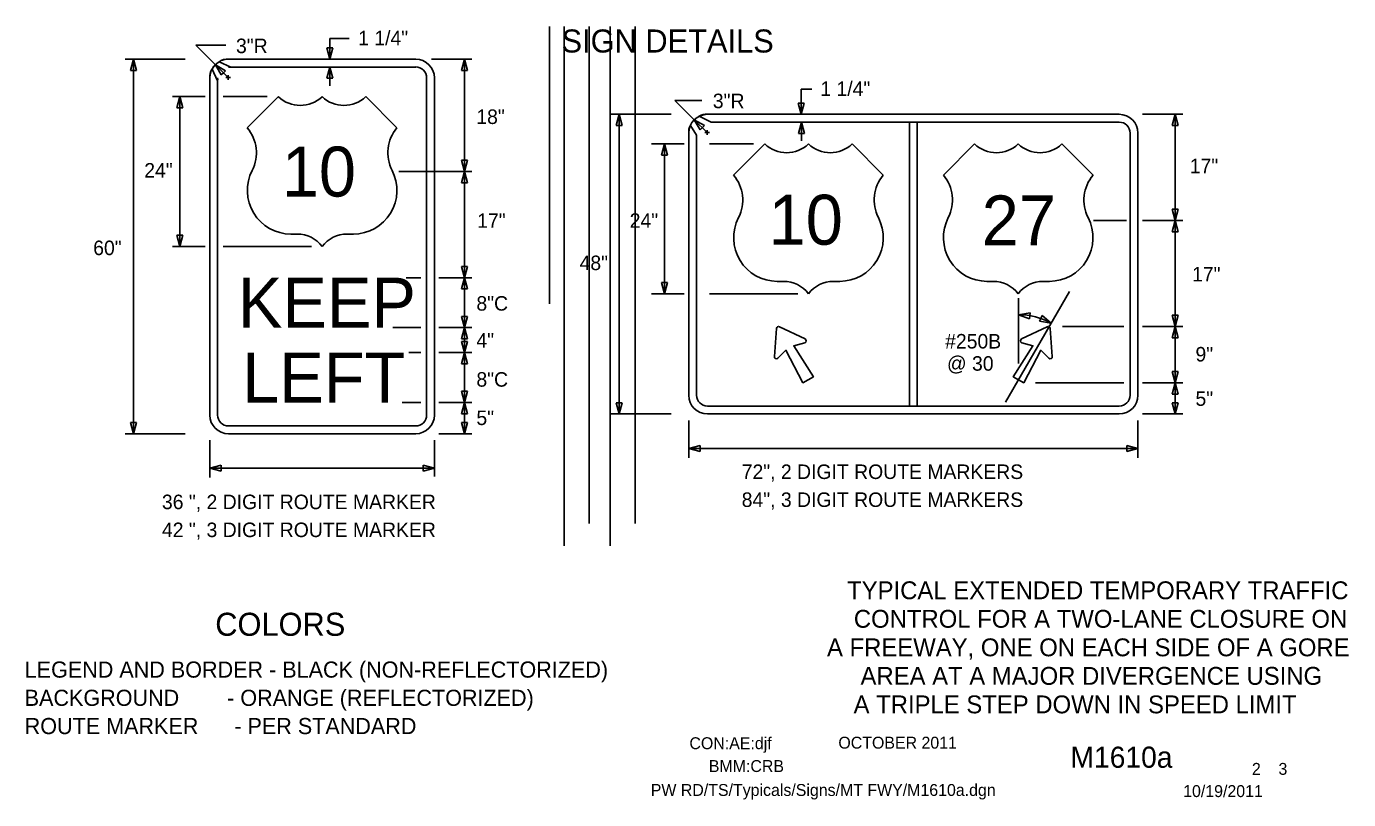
# Model space of a CAD drawing. Extents: x 16554 to 19508, y 5694 to 7079.
# Drawn here: x 17774 to 18463, y 5932 to 6334 of the extents above; entities that cross this region are included whole.
import ezdxf

# ---------------------------------------------------------------- set-up
doc = ezdxf.new("R2010")
doc.units = 0
for name, color, linetype in [('ALI_LEGAL_EX', 7, 'Continuous'), ('BORDER', 7, 'Continuous'), ('BORDER_SIGNAL_WO', 7, 'Continuous'), ('TRAFFIC_SIGNS_PR', 7, 'Continuous'), ('TYPICAL_EX', 7, 'Continuous'), ('TYPICAL_TEXT_DIMEN_PR', 7, 'Continuous')]:
    doc.layers.add(name, color=color, linetype=linetype)

msp = doc.modelspace()

# ---------------------------------------------------------------- linework, layer by layer
at = {"layer": 'ALI_LEGAL_EX'}
for p, q in [((18046.81, 6189.84), (18046.81, 6334.29)), ((18054.48, 6334.29), (18054.48, 6206.79)), ((18054.48, 6334.29), (18054.48, 6063.94)), ((18067.45, 6075.61), (18067.45, 6334.29)), ((18078.48, 6334.29), (18078.48, 6206.79)), ((18078.48, 6334.29), (18078.48, 6063.94)), ((18091.45, 6075.61), (18091.45, 6334.29))]:
    msp.add_line(p, q, dxfattribs=at)
at = {"layer": 'TRAFFIC_SIGNS_PR'}
for p, q in [((17879.58, 6317.25), (17977.08, 6317.25)), ((17872, 6313.63), (17870.99, 6312.12)), ((17871.02, 6312.05), (17873.89, 6306.01)), ((17880.78, 6313.18), (17874.69, 6315.93)), ((17977.08, 6313.18), (17879.58, 6313.18)), ((17869.83, 6132), (17869.83, 6307.5)), ((17873.89, 6307.5), (17873.89, 6132)), ((17982.77, 6132), (17982.77, 6307.5)), ((17986.83, 6307.5), (17986.83, 6132)), ((18120.27, 6282.81), (18123.41, 6277.76)), ((18131.06, 6284.5), (18124.82, 6287.51)), ((18129.1, 6288.55), (18343.6, 6288.55)), ((18129.1, 6288.55), (18343.6, 6288.55)), ((18131.04, 6284.49), (18234.32, 6284.49)), ((18343.6, 6284.49), (18131.04, 6284.49)), ((18234.32, 6284.49), (18234.32, 6136.61)), ((18238.38, 6284.49), (18238.38, 6136.61)), ((18238.38, 6284.49), (18343.6, 6284.49)), ((18119.35, 6278.8), (18119.35, 6142.3)), ((18119.35, 6142.3), (18119.35, 6278.8)), ((18123.41, 6277.75), (18123.41, 6142.3)), ((18123.41, 6277.75), (18123.41, 6142.3)), ((18349.29, 6278.8), (18349.29, 6233.05)), ((18349.29, 6142.3), (18349.29, 6278.8)), ((18353.35, 6278.8), (18353.35, 6142.3)), ((18353.35, 6278.8), (18353.35, 6142.3)), ((18349.29, 6233.05), (18349.29, 6142.3)), ((18163.95, 6162.41), (18165.1, 6177.12)), ((18166.62, 6177.99), (18179.93, 6171.63)), ((18306.08, 6177.99), (18292.77, 6171.63)), ((18308.75, 6162.41), (18307.6, 6177.12)), ((18129.1, 6136.61), (18343.6, 6136.61)), ((18129.1, 6132.55), (18343.6, 6132.55)), ((18343.6, 6132.55), (18129.1, 6132.55)), ((17879.58, 6126.31), (17977.08, 6126.31)), ((17977.08, 6122.25), (17879.58, 6122.25))]:
    msp.add_line(p, q, dxfattribs=at)
for points in [[(18131.04, 6284.49), (18131.03, 6284.49)], [(18123.41, 6277.76), (18123.41, 6277.75)], [(18179.77, 6169.66), (18174.04, 6168.09), (18184.26, 6151.92), (18178.86, 6148.8), (18169.97, 6165.74), (18165.74, 6161.57)], [(18292.93, 6169.66), (18298.66, 6168.09), (18288.44, 6151.92), (18293.84, 6148.8), (18302.73, 6165.74), (18306.96, 6161.57)]]:
    msp.add_lwpolyline(points, dxfattribs=at)
msp.add_lwpolyline([(18234.32, 6284.49), (18238.38, 6284.49), (18238.38, 6136.61), (18234.32, 6136.61)], close=True, dxfattribs=at)
for centre, radius, start, end in [((17879.58, 6307.5), 9.75, 90, 180), ((17878.99, 6309.67), 7.6, 85.58319, 124.53531), ((17977.08, 6307.5), 9.75, 0, 90), ((17876.86, 6308.09), 7.06, 145.86811, 184.82317), ((17880.18, 6317.61), 4.47, 262.2432, 277.7568), ((17977.08, 6307.5), 5.69, 0, 90), ((17868.43, 6306.75), 5.51, 352.24294, 7.75653), ((18125.48, 6279.5), 6.17, 147.60925, 186.56283), ((18129.1, 6278.8), 9.75, 90, 180), ((18129.1, 6278.8), 9.75, 90, 180), ((18128.42, 6281.98), 6.6, 84.11162, 123.06374), ((18130.04, 6291.67), 7.24, 277.81035, 278.05403), ((18343.6, 6278.8), 9.75, 0, 90), ((18343.6, 6278.8), 9.75, 0, 90), ((18343.6, 6278.8), 5.69, 0, 89.99421), ((18343.6, 6278.8), 5.69, 0, 90), ((18166.16, 6177.04), 1.06, 64.48226, 175.51774), ((18306.54, 6177.04), 1.06, 4.48226, 115.51774), ((18179.47, 6170.68), 1.06, 285.9885, 64.48226), ((18293.23, 6170.68), 1.06, 115.51774, 254.0115), ((18165.01, 6162.33), 1.06, 175.51775, 314.01151), ((18307.69, 6162.33), 1.06, 225.98849, 4.48225), ((18129.1, 6142.3), 9.75, 180, 270), ((18129.1, 6142.3), 9.75, 180, 270), ((18129.1, 6142.3), 5.69, 180, 270), ((18129.1, 6142.3), 5.69, 180, 270), ((18343.6, 6142.3), 9.75, 270, 0), ((18343.6, 6142.3), 5.69, 270, 0), ((18343.6, 6142.3), 9.75, 270, 0), ((18343.6, 6142.3), 5.69, 270, 0), ((17879.58, 6132), 9.75, 180, 270), ((17879.58, 6132), 5.69, 180, 270), ((17977.08, 6132), 5.69, 270, 0), ((17977.08, 6132), 9.75, 270, 0)]:
    msp.add_arc(centre, radius, start, end, dxfattribs=at)
at = {"layer": 'TYPICAL_EX'}
for p, q in [((17889.33, 6281.5), (17905.58, 6297.75)), ((17967.33, 6281.5), (17951.08, 6297.75)), ((18142.71, 6256.89), (18158.96, 6273.14)), ((18220.71, 6256.89), (18204.46, 6273.14)), ((18251.99, 6256.89), (18268.24, 6273.14)), ((18329.99, 6256.89), (18313.74, 6273.14)), ((17912.06, 6226.21), (17915.31, 6226.21)), ((17944.6, 6226.21), (17941.35, 6226.21)), ((18165.44, 6201.6), (18168.69, 6201.6)), ((18197.98, 6201.6), (18194.73, 6201.6)), ((18274.72, 6201.6), (18277.97, 6201.6)), ((18307.26, 6201.6), (18304.01, 6201.6))]:
    msp.add_line(p, q, dxfattribs=at)
for centre, radius, start, end in [((17916.95, 6309.58), 16.42, 226.14041, 313.85958), ((17939.7, 6309.59), 16.42, 226.14042, 313.85959), ((17873.93, 6268.49), 20.16, 333.09768, 40.19361), ((17982.73, 6268.49), 20.16, 139.80639, 206.90233), ((18170.34, 6284.97), 16.42, 226.14041, 313.85958), ((18193.09, 6284.97), 16.42, 226.14042, 313.85959), ((18279.62, 6284.97), 16.42, 226.14041, 313.85958), ((18302.36, 6284.97), 16.42, 226.14042, 313.85959), ((17912.1, 6248.93), 22.73, 152.6698, 269.90132), ((17944.56, 6248.93), 22.73, 270.09868, 27.3302), ((18127.31, 6243.88), 20.16, 333.09768, 40.19361), ((18236.11, 6243.88), 20.16, 139.80639, 206.90233), ((18236.59, 6243.88), 20.16, 333.09768, 40.19361), ((18345.39, 6243.88), 20.16, 139.80639, 206.90233), ((18165.48, 6224.32), 22.73, 152.6698, 269.90132), ((18197.94, 6224.32), 22.73, 270.09868, 27.3302), ((18274.76, 6224.32), 22.73, 152.6698, 269.90132), ((18307.22, 6224.32), 22.73, 270.09868, 27.3302), ((17915.35, 6209.93), 16.28, 37.1038, 90.13853), ((17941.31, 6209.93), 16.28, 89.86147, 142.8962), ((18168.73, 6185.32), 16.28, 37.1038, 90.13853), ((18194.69, 6185.32), 16.28, 89.86147, 142.8962), ((18278.01, 6185.32), 16.28, 37.1038, 90.13853), ((18303.97, 6185.32), 16.28, 89.86147, 142.8962)]:
    msp.add_arc(centre, radius, start, end, dxfattribs=at)
at = {"layer": 'TYPICAL_TEXT_DIMEN_PR'}
for p, q in [((17878.2, 6324.53), (17862.54, 6324.53)), ((17862.54, 6324.53), (17872.78, 6314.29)), ((17932.3, 6328.01), (17932.3, 6317.25)), ((17932.3, 6328.01), (17942.41, 6328.01)), ((17857, 6317.25), (17825.71, 6317.25)), ((17828.47, 6311.38), (17830.04, 6317.25)), ((17830.04, 6317.25), (17830.04, 6122.25)), ((17830.04, 6317.25), (17831.62, 6311.38)), ((17932.3, 6317.25), (17930.73, 6323.11)), ((17930.73, 6323.11), (17932.3, 6323.11)), ((17932.3, 6323.11), (17933.87, 6323.11)), ((17933.87, 6323.11), (17932.3, 6317.25)), ((17985.37, 6317.25), (18006.33, 6317.25)), ((18000.86, 6311.38), (18002.43, 6317.25)), ((18002.43, 6317.25), (18002.43, 6258.75)), ((18002.43, 6317.25), (18004, 6311.38)), ((17830.04, 6311.38), (17828.47, 6311.38)), ((17831.62, 6311.38), (17830.04, 6311.38)), ((17872.78, 6314.29), (17879.34, 6307.74)), ((17875.81, 6309.04), (17872.78, 6314.29)), ((17872.78, 6314.29), (17878.04, 6311.26)), ((17876.92, 6310.15), (17875.81, 6309.04)), ((17878.04, 6311.26), (17876.92, 6310.15)), ((17930.78, 6307.32), (17932.35, 6313.18)), ((17932.35, 6313.18), (17932.35, 6303.43)), ((17932.35, 6313.18), (17933.92, 6307.32)), ((18002.43, 6311.38), (18000.86, 6311.38)), ((18004, 6311.38), (18002.43, 6311.38)), ((17878.13, 6307.74), (17880.55, 6307.74)), ((17879.34, 6306.53), (17879.34, 6308.95)), ((17932.35, 6307.32), (17930.78, 6307.32)), ((17933.92, 6307.32), (17932.35, 6307.32)), ((17867.46, 6297.75), (17850.33, 6297.75)), ((17852.65, 6291.88), (17854.23, 6297.75)), ((17854.23, 6297.75), (17854.23, 6219.75)), ((17854.23, 6297.75), (17855.8, 6291.88)), ((17899.7, 6297.75), (17876.82, 6297.75)), ((18126.24, 6295.83), (18112.06, 6295.83)), ((18112.06, 6295.83), (18122.21, 6285.69)), ((18177.96, 6301.7), (18177.96, 6288.55)), ((18177.96, 6301.7), (18183.48, 6301.7)), ((17854.23, 6291.88), (17852.65, 6291.88)), ((17855.8, 6291.88), (17854.23, 6291.88)), ((18177.96, 6288.55), (18176.39, 6294.41)), ((18176.39, 6294.41), (18177.96, 6294.41)), ((18177.96, 6294.41), (18179.53, 6294.41)), ((18179.53, 6294.41), (18177.96, 6288.55)), ((18110.12, 6288.55), (18078.82, 6288.55)), ((18081.59, 6282.69), (18083.16, 6288.55)), ((18083.16, 6282.69), (18081.59, 6282.69)), ((18083.16, 6288.55), (18083.16, 6132.55)), ((18083.16, 6288.55), (18084.73, 6282.69)), ((18084.73, 6282.69), (18083.16, 6282.69)), ((18122.21, 6285.69), (18128.86, 6279.04)), ((18125.25, 6280.43), (18122.21, 6285.68)), ((18122.21, 6285.68), (18127.47, 6282.65)), ((18127.47, 6282.65), (18126.36, 6281.54)), ((18176.44, 6278.62), (18178.01, 6284.49)), ((18176.44, 6278.62), (18178.01, 6284.49)), ((18178.01, 6284.49), (18178.01, 6274.74)), ((18178.01, 6284.49), (18179.58, 6278.62)), ((18178.01, 6284.49), (18179.58, 6278.62)), ((18355.72, 6288.55), (18376.68, 6288.55)), ((18371.22, 6282.69), (18372.79, 6288.55)), ((18372.79, 6282.69), (18371.22, 6282.69)), ((18372.78, 6288.55), (18372.78, 6233.3)), ((18372.79, 6288.55), (18374.36, 6282.69)), ((18374.36, 6282.69), (18372.79, 6282.69)), ((18126.36, 6281.54), (18125.25, 6280.43)), ((18127.65, 6279.04), (18130.07, 6279.04)), ((18128.86, 6277.83), (18128.86, 6280.25)), ((18178.01, 6278.62), (18176.44, 6278.62)), ((18178.01, 6278.62), (18176.44, 6278.62)), ((18179.58, 6278.62), (18178.01, 6278.62)), ((18179.58, 6278.62), (18178.01, 6278.62)), ((18116.98, 6273.14), (18099.85, 6273.14)), ((18105.15, 6267.27), (18106.72, 6273.14)), ((18106.72, 6273.14), (18106.72, 6195.14)), ((18106.72, 6273.14), (18108.29, 6267.27)), ((18153.08, 6273.14), (18130.2, 6273.14)), ((18002.43, 6258.75), (18000.86, 6264.61)), ((18000.86, 6264.61), (18002.43, 6264.61)), ((18002.43, 6264.61), (18004, 6264.61)), ((18004, 6264.61), (18002.43, 6258.75)), ((18106.72, 6267.27), (18105.15, 6267.27)), ((18108.29, 6267.27), (18106.72, 6267.27)), ((17968.22, 6258.75), (18006.33, 6258.75)), ((18000.86, 6252.88), (18002.43, 6258.75)), ((18002.43, 6258.75), (18002.43, 6203.5)), ((18002.43, 6258.75), (18004, 6252.88)), ((18002.43, 6252.88), (18000.86, 6252.88)), ((18004, 6252.88), (18002.43, 6252.88)), ((18372.79, 6233.3), (18371.22, 6239.16)), ((18371.22, 6239.16), (18372.79, 6239.16)), ((18372.79, 6239.16), (18374.36, 6239.16)), ((18374.36, 6239.16), (18372.79, 6233.3)), ((18330.17, 6233.3), (18347.32, 6233.3)), ((18355.72, 6233.3), (18376.68, 6233.3)), ((18371.22, 6227.44), (18372.79, 6233.3)), ((18372.79, 6227.44), (18371.22, 6227.44)), ((18372.78, 6233.3), (18372.78, 6178.05)), ((18372.79, 6233.3), (18374.36, 6227.44)), ((18374.36, 6227.44), (18372.79, 6227.44)), ((17854.23, 6219.75), (17852.65, 6225.61)), ((17852.65, 6225.61), (17854.23, 6225.61)), ((17854.23, 6225.61), (17855.8, 6225.61)), ((17855.8, 6225.61), (17854.23, 6219.75)), ((17867.46, 6219.75), (17850.33, 6219.75)), ((17922.82, 6219.75), (17876.82, 6219.75)), ((18002.43, 6203.5), (18000.86, 6209.36)), ((18000.86, 6209.36), (18002.43, 6209.36)), ((18002.43, 6209.36), (18004, 6209.36)), ((18004, 6209.36), (18002.43, 6203.5)), ((17972.16, 6203.5), (17979.84, 6203.5)), ((17989.2, 6203.5), (18006.33, 6203.5)), ((18000.86, 6197.63), (18002.43, 6203.5)), ((18002.43, 6203.5), (18002.43, 6177.5)), ((18002.43, 6203.5), (18004, 6197.63)), ((18106.72, 6195.14), (18105.15, 6201)), ((18105.15, 6201), (18106.72, 6201)), ((18106.72, 6201), (18108.29, 6201)), ((18108.29, 6201), (18106.72, 6195.14)), ((18002.43, 6197.63), (18000.86, 6197.63)), ((18004, 6197.63), (18002.43, 6197.63)), ((18116.98, 6195.14), (18099.85, 6195.14)), ((18176.2, 6195.14), (18130.2, 6195.14)), ((18284.38, 6138.65), (18317.62, 6196.24)), ((18291.14, 6158.8), (18291.14, 6192.8)), ((18002.43, 6177.5), (18000.86, 6183.36)), ((18000.86, 6183.36), (18002.43, 6183.36)), ((18002.43, 6183.36), (18004, 6183.36)), ((18004, 6183.36), (18002.43, 6177.5)), ((18291.17, 6184.24), (18297.16, 6185.2)), ((18296.84, 6182.08), (18291.17, 6184.24)), ((18297, 6183.64), (18296.84, 6182.08)), ((18297.16, 6185.2), (18297, 6183.64)), ((18302.15, 6180.92), (18302.84, 6182.33)), ((18308.12, 6179.79), (18302.15, 6180.92)), ((18302.84, 6182.33), (18303.52, 6183.75)), ((18303.52, 6183.75), (18308.12, 6179.79)), ((18372.79, 6178.05), (18371.22, 6183.91)), ((18371.22, 6183.91), (18372.79, 6183.91)), ((18372.79, 6183.91), (18374.36, 6183.91)), ((18374.36, 6183.91), (18372.79, 6178.05)), ((17965.14, 6177.5), (17979.84, 6177.5)), ((17989.2, 6177.5), (18006.33, 6177.5)), ((18000.86, 6171.63), (18002.43, 6177.5)), ((18002.43, 6177.5), (18002.43, 6164.5)), ((18002.43, 6177.5), (18004, 6171.63)), ((18314.09, 6178.05), (18345.96, 6178.05)), ((18355.72, 6178.05), (18376.68, 6178.05)), ((18371.22, 6172.19), (18372.79, 6178.05)), ((18372.79, 6172.19), (18371.22, 6172.19)), ((18372.78, 6178.05), (18372.78, 6148.8)), ((18372.79, 6178.05), (18374.36, 6172.19)), ((18374.36, 6172.19), (18372.79, 6172.19)), ((18002.43, 6171.63), (18000.86, 6171.63)), ((18002.43, 6164.5), (18000.86, 6170.36)), ((18000.86, 6170.36), (18002.43, 6170.36)), ((18004, 6171.63), (18002.43, 6171.63)), ((18002.43, 6170.36), (18004, 6170.36)), ((18004, 6170.36), (18002.43, 6164.5)), ((17973.49, 6164.5), (17979.84, 6164.5)), ((17989.2, 6164.5), (18006.33, 6164.5)), ((18000.86, 6158.63), (18002.43, 6164.5)), ((18002.43, 6158.63), (18000.86, 6158.63)), ((18002.43, 6164.5), (18002.43, 6138.5)), ((18002.43, 6164.5), (18004, 6158.63)), ((18004, 6158.63), (18002.43, 6158.63)), ((18372.79, 6148.8), (18371.22, 6154.66)), ((18371.22, 6154.66), (18372.79, 6154.66)), ((18372.79, 6154.66), (18374.36, 6154.66)), ((18374.36, 6154.66), (18372.79, 6148.8)), ((18002.43, 6138.5), (18000.86, 6144.36)), ((18000.86, 6144.36), (18002.43, 6144.36)), ((18002.43, 6144.36), (18004, 6144.36)), ((18004, 6144.36), (18002.43, 6138.5)), ((18299.96, 6148.8), (18345.96, 6148.8)), ((18355.72, 6148.8), (18376.68, 6148.8)), ((18371.22, 6142.94), (18372.79, 6148.8)), ((18372.78, 6148.8), (18372.78, 6132.55)), ((18372.79, 6148.8), (18374.36, 6142.94)), ((17969.99, 6138.5), (17979.84, 6138.5)), ((17989.2, 6138.5), (18006.33, 6138.5)), ((18000.86, 6132.63), (18002.43, 6138.5)), ((18002.43, 6138.5), (18002.43, 6122.25)), ((18002.43, 6138.5), (18004, 6132.63)), ((18083.16, 6132.55), (18081.59, 6138.41)), ((18081.59, 6138.41), (18083.16, 6138.41)), ((18083.16, 6138.41), (18084.73, 6138.41)), ((18084.73, 6138.41), (18083.16, 6132.55)), ((18372.79, 6142.94), (18371.22, 6142.94)), ((18372.79, 6132.55), (18371.22, 6138.41)), ((18371.22, 6138.41), (18372.79, 6138.41)), ((18374.36, 6142.94), (18372.79, 6142.94)), ((18372.79, 6138.41), (18374.36, 6138.41)), ((18374.36, 6138.41), (18372.79, 6132.55)), ((18002.43, 6132.63), (18000.86, 6132.63)), ((18004, 6132.63), (18002.43, 6132.63)), ((18110.12, 6132.55), (18078.82, 6132.55)), ((18355.72, 6132.55), (18372.85, 6132.55)), ((18355.72, 6132.55), (18376.68, 6132.55)), ((18355.72, 6132.55), (18372.85, 6132.55)), ((17830.04, 6122.25), (17828.47, 6128.11)), ((17828.47, 6128.11), (17830.04, 6128.11)), ((17830.04, 6128.11), (17831.62, 6128.11)), ((17831.62, 6128.11), (17830.04, 6122.25)), ((18002.43, 6122.25), (18000.86, 6128.11)), ((18000.86, 6128.11), (18002.43, 6128.11)), ((18002.43, 6128.11), (18004, 6128.11)), ((18004, 6128.11), (18002.43, 6122.25)), ((18119.35, 6129.2), (18119.35, 6109.64)), ((18353.35, 6129.2), (18353.35, 6109.64)), ((17857, 6122.25), (17825.71, 6122.25)), ((17869.83, 6118.9), (17869.83, 6099.55)), ((17986.83, 6118.9), (17986.83, 6100.01)), ((17989.2, 6122.25), (18006.33, 6122.25)), ((18119.35, 6114.58), (18125.21, 6116.15)), ((18119.35, 6114.58), (18353.35, 6114.58)), ((18125.21, 6113.01), (18119.35, 6114.58)), ((18125.21, 6116.15), (18125.21, 6114.58)), ((18125.21, 6114.58), (18125.21, 6113.01)), ((18347.49, 6114.58), (18347.49, 6116.15)), ((18347.49, 6116.15), (18353.35, 6114.58)), ((18353.35, 6114.58), (18347.49, 6113.01)), ((18347.49, 6113.01), (18347.49, 6114.58)), ((17869.83, 6104.27), (17875.69, 6105.85)), ((17869.83, 6104.27), (17986.83, 6104.27)), ((17875.69, 6102.7), (17869.83, 6104.27)), ((17875.69, 6105.85), (17875.69, 6104.27)), ((17875.69, 6104.27), (17875.69, 6102.7)), ((17980.97, 6104.27), (17980.97, 6105.85)), ((17980.97, 6105.85), (17986.83, 6104.27)), ((17986.83, 6104.27), (17980.97, 6102.7)), ((17980.97, 6102.7), (17980.97, 6104.27))]:
    msp.add_line(p, q, dxfattribs=at)
msp.add_arc((18291.33, 6149.8), 34.39, 60.74521, 90.32117, dxfattribs=at)

# ---------------------------------------------------------------- texts
at = {"layer": 'BORDER'}
for s, p in [('TYPICAL EXTENDED TEMPORARY TRAFFIC', (18201.85, 6036.12)), ('CONTROL FOR A TWO-LANE CLOSURE ON', (18205.35, 6021.27)), ('A FREEWAY, ONE ON EACH SIDE OF A GORE', (18191.37, 6006.42)), ('AREA AT A MAJOR DIVERGENCE USING', (18208.84, 5991.57)), ('A TRIPLE STEP DOWN IN SPEED LIMIT', (18205.22, 5976.72))]:
    msp.add_text(s, height=9.3, dxfattribs=at).set_placement(p)
at = {"layer": 'BORDER_SIGNAL_WO'}
for s, height, p in [('CON:AE:djf  ', 6.2, (18119.69, 5958.06)), ('    OCTOBER 2011    ', 6.2, (18188.08, 5958.34)), ('    M1610a   ', 11, (18301.86, 5948.38)), ('BMM:CRB   ', 6.2, (18129.81, 5946.17)), (' 2    3 ', 6.2, (18410.45, 5944.7)), ('PW RD/TS/Typicals/Signs/MT FWY/M1610a.dgn      ', 6.2, (18099.55, 5933.71)), ('10/19/2011    ', 6.2, (18376.93, 5933.13))]:
    msp.add_text(s, height=height, dxfattribs=at).set_placement(p)
at = {"layer": 'TRAFFIC_SIGNS_PR'}
for s, p in [('10', (17907.3, 6245.75)), ('10', (18160.95, 6220.68)), ('27', (18271.96, 6220.32)), ('KEEP', (17884.43, 6177.5)), ('LEFT', (17886.67, 6138.5))]:
    msp.add_text(s, height=26, dxfattribs=at).set_placement(p)
at = {"layer": 'TYPICAL_TEXT_DIMEN_PR'}
for s, height, p in [('1 1/4"', 7.55, (17947.1, 6324.5)), ('SIGN DETAILS', 12, (18053.06, 6320.72)), ('3"R', 7.55, (17883.47, 6320.41)), ('1 1/4"', 7.55, (18187.89, 6298.12)), ('3"R', 7.55, (18131.88, 6291.75)), ('18"', 7.55, (18008.67, 6283.52)), ('24"', 7.55, (17835.67, 6255.63)), ('17"', 7.55, (18380.36, 6257.91)), ('17"', 7.55, (18009.13, 6229.47)), ('24"', 7.55, (18088.58, 6229.47)), ('60"', 7.55, (17809.07, 6215.26)), ('48"', 7.55, (18062.46, 6207.45)), ('17"', 7.55, (18381.56, 6201.55)), ('8"C', 7.55, (18008.71, 6186.35)), ('4" ', 7.55, (18008.71, 6167.09)), ('#250B', 7.55, (18252.91, 6166.64)), ('9"', 7.55, (18383.34, 6159.89)), ('@ 30', 7.55, (18253.86, 6155.09)), ('8"C', 7.55, (18008.71, 6146.77)), ('5"', 7.55, (18383.34, 6136.79)), ('5" ', 7.55, (18008.71, 6126.79)), ('72", 2 DIGIT ROUTE MARKERS', 7.55, (18146.93, 6098.71)), ('36 ", 2 DIGIT ROUTE MARKER', 7.55, (17844.88, 6083.01)), ('84", 3 DIGIT ROUTE MARKERS', 7.55, (18146.93, 6084.16)), ('42 ", 3 DIGIT ROUTE MARKER', 7.55, (17844.88, 6068.47)), ('COLORS', 12, (17872.65, 6017.08)), ('LEGEND AND BORDER - BLACK (NON-REFLECTORIZED)', 8.4, (17773.37, 5995.3)), ('BACKGROUND        - ORANGE (REFLECTORIZED)', 8.4, (17773.37, 5980.6)), ('ROUTE MARKER      - PER STANDARD', 8.4, (17773.37, 5965.9))]:
    msp.add_text(s, height=height, dxfattribs=at).set_placement(p)

doc.saveas('drawing.dxf')
